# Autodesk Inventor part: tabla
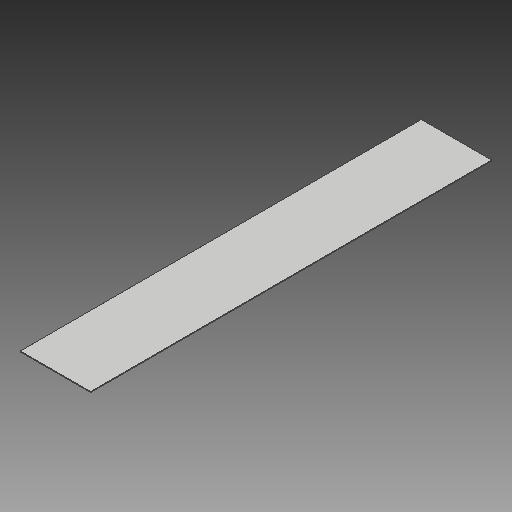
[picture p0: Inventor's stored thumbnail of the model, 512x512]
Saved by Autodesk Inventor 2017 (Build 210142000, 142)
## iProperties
Created: 2017-11
Part Number: tabla
Material: Generic
Document SubType Name: Modeling
Designer: iusti
Density: 1 g/cm^3
Appearance: Default
Mass: 329800 g
Surface Area: 334360 cm^2
Volume: 329800 cm^3
Author: iusti
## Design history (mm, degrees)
sketch "Sketch1"
  geometry: L1 (850, 4850)-(-850, 4850); L2 (-850, 4850)-(-850, -4850); L3 (-850, -4850)-(850, -4850); L4 (850, -4850)-(850, 4850); L5 (850, 4850)-(-850, -4850); L6 (-850, 4850)-(850, -4850); 1 further point
  constraints: 12 end point, 2 midpoint, 2 parallel, 1 horizontal, 1 perpendicular
  dimensions: "d0" = 9700 distance of L3.end L1.start; "d1" = 1700 distance of L2.end L3.end
extrude "Extrusion1" new body sketch "Sketch1" distance "d2" = 20; taper "d3" = 0 deg
body "Solid1"
